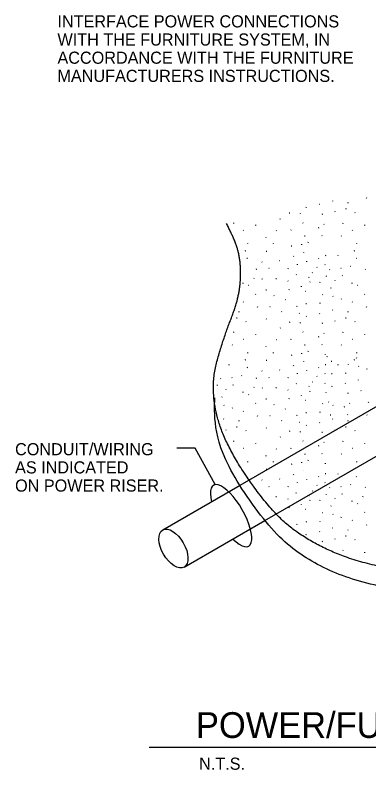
# Model space of a CAD drawing. Extents: x 10309.1 to 10402.7, y 9934 to 9975.2.
# Drawn here: x 10356.1 to 10373.62, y 9935.44 to 9972.81 of the extents above; entities that cross this region are included whole.
import ezdxf

# ---------------------------------------------------------------- set-up
doc = ezdxf.new("R2010")
doc.units = 0
for name, color, linetype in [('G-ANNO-TEXT', 7, 'Continuous'), ('G-DETL-LINE', 7, 'Continuous'), ('G-DETL-OTLN', 7, 'Continuous'), ('G-DETL-PATT', 7, 'Continuous')]:
    doc.layers.add(name, color=color, linetype=linetype)

msp = doc.modelspace()

# ---------------------------------------------------------------- linework, layer by layer
at = {"layer": 'G-ANNO-TEXT'}
msp.add_line((10362.735, 9936.566), (10402.697, 9936.566), dxfattribs=at)
msp.add_lwpolyline([(10366.014, 9949.569), (10365.012, 9951.367), (10364.112, 9951.367)], dxfattribs=at)
msp.add_ellipse((10366.796, 9948.027), major_axis=(-0.869, 1.505), ratio=0.360031, start_param=2.215953, end_param=7.186541, dxfattribs=at)
at = {"layer": 'G-DETL-LINE'}
for p, q in [((10367.242, 9949.532), (10382.211, 9958.175)), ((10368.469, 9947.792), (10383.177, 9956.284)), ((10363.409, 9947.32), (10367.242, 9949.532)), ((10364.47, 9945.483), (10368.469, 9947.792))]:
    msp.add_line(p, q, dxfattribs=at)
msp.add_ellipse((10363.94, 9946.401), major_axis=(0.53, -0.919), ratio=0.531703, dxfattribs=at)
at = {"layer": 'G-DETL-OTLN'}
for p, q in [((10371.839, 9963.603), (10371.828, 9963.614)), ((10373.506, 9963.752), (10373.516, 9963.78)), ((10370.514, 9963.286), (10370.524, 9963.314)), ((10371.193, 9963.43), (10371.178, 9963.444)), ((10372.488, 9963.214), (10372.459, 9963.208)), ((10372.59, 9963.504), (10372.599, 9963.532)), ((10369.705, 9963.005), (10369.676, 9962.999)), ((10370.226, 9962.968), (10370.235, 9962.996)), ((10371.319, 9962.953), (10371.291, 9962.939)), ((10371.957, 9963.067), (10371.943, 9963.081)), ((10372.938, 9963.028), (10372.924, 9963.042)), ((10366.928, 9962.498), (10366.938, 9962.526)), ((10369.232, 9962.707), (10369.241, 9962.735)), ((10370.365, 9962.519), (10370.351, 9962.533)), ((10371.403, 9962.448), (10371.389, 9962.462)), ((10372.328, 9962.498), (10372.338, 9962.526)), ((10367.415, 9962.157), (10367.386, 9962.151)), ((10368.015, 9962.394), (10368.024, 9962.422)), ((10369.043, 9962.127), (10369.029, 9962.141)), ((10369.755, 9962.159), (10369.764, 9962.187)), ((10371.136, 9962.28), (10371.108, 9962.266)), ((10372.815, 9962.157), (10372.786, 9962.151)), ((10373.415, 9962.394), (10373.424, 9962.422)), ((10368.525, 9961.78), (10368.534, 9961.808)), ((10370.464, 9961.87), (10370.435, 9961.863)), ((10371.305, 9961.887), (10371.291, 9961.901)), ((10372.258, 9961.866), (10372.244, 9961.88)), ((10367.622, 9961.48), (10367.631, 9961.508)), ((10368.891, 9961.48), (10368.901, 9961.508)), ((10369.797, 9961.373), (10369.768, 9961.367)), ((10370.292, 9961.441), (10370.301, 9961.469)), ((10370.619, 9961.562), (10370.629, 9961.591)), ((10373.022, 9961.48), (10373.031, 9961.508)), ((10367.507, 9961.138), (10367.478, 9961.132)), ((10368.567, 9961.112), (10368.538, 9961.106)), ((10370.404, 9961.057), (10370.39, 9961.071)), ((10372.907, 9961.138), (10372.878, 9961.132)), ((10367.611, 9960.76), (10367.582, 9960.754)), ((10368.338, 9960.582), (10368.324, 9960.596)), ((10369.213, 9960.639), (10369.199, 9960.653)), ((10369.886, 9960.853), (10369.895, 9960.881)), ((10370.541, 9960.596), (10370.55, 9960.624)), ((10371.136, 9960.751), (10371.122, 9960.765)), ((10371.48, 9960.903), (10371.451, 9960.897)), ((10372.098, 9960.894), (10372.102, 9960.907)), ((10373.011, 9960.76), (10372.982, 9960.754)), ((10368.056, 9960.231), (10368.028, 9960.217)), ((10368.675, 9960.26), (10368.661, 9960.274)), ((10369.624, 9960.253), (10369.634, 9960.281)), ((10370.082, 9960.448), (10370.092, 9960.476)), ((10371.052, 9960.316), (10371.038, 9960.33)), ((10371.46, 9960.456), (10371.446, 9960.47)), ((10371.685, 9960.203), (10371.671, 9960.217)), ((10372.247, 9960.26), (10372.233, 9960.274)), ((10372.725, 9960.358), (10372.711, 9960.372)), ((10373.456, 9960.231), (10373.428, 9960.217)), ((10370.017, 9959.949), (10370.027, 9959.977)), ((10370.645, 9959.818), (10370.655, 9959.846)), ((10370.815, 9960.063), (10370.827, 9960.057)), ((10370.827, 9960.057), (10370.832, 9960.05)), ((10371.518, 9959.871), (10371.527, 9959.899)), ((10372.303, 9959.897), (10372.312, 9959.925)), ((10367.386, 9959.527), (10367.396, 9959.555)), ((10367.923, 9959.766), (10367.933, 9959.794)), ((10368.342, 9959.736), (10368.351, 9959.764)), ((10369.038, 9959.76), (10369.009, 9959.754)), ((10369.619, 9959.639), (10369.605, 9959.653)), ((10370.698, 9959.583), (10370.707, 9959.611)), ((10371.19, 9959.579), (10371.199, 9959.607)), ((10371.957, 9959.678), (10371.943, 9959.692)), ((10372.786, 9959.527), (10372.796, 9959.555)), ((10367.669, 9959.417), (10367.655, 9959.431)), ((10368.541, 9959.198), (10368.512, 9959.192)), ((10369.676, 9959.213), (10369.686, 9959.241)), ((10370.278, 9959.357), (10370.288, 9959.385)), ((10370.503, 9959.133), (10370.475, 9959.127)), ((10371.739, 9959.292), (10371.749, 9959.32)), ((10373.069, 9959.417), (10373.055, 9959.431)), ((10368.023, 9958.986), (10368.009, 9959)), ((10368.926, 9958.921), (10368.912, 9958.935)), ((10369.496, 9958.715), (10369.467, 9958.709)), ((10371.342, 9958.96), (10371.328, 9958.974)), ((10371.852, 9958.881), (10371.838, 9958.896)), ((10372.25, 9958.743), (10372.259, 9958.771)), ((10373.423, 9958.986), (10373.409, 9959)), ((10367.408, 9958.594), (10367.394, 9958.608)), ((10368.106, 9958.352), (10368.116, 9958.38)), ((10368.737, 9958.376), (10368.708, 9958.37)), ((10370.056, 9958.391), (10370.065, 9958.419)), ((10370.53, 9958.519), (10370.501, 9958.513)), ((10371.203, 9958.534), (10371.212, 9958.563)), ((10372.808, 9958.594), (10372.794, 9958.608)), ((10373.506, 9958.352), (10373.516, 9958.38)), ((10367.19, 9958.104), (10367.199, 9958.132)), ((10369.297, 9958.117), (10369.306, 9958.145)), ((10370.182, 9958.033), (10370.168, 9958.047)), ((10371.193, 9958.03), (10371.178, 9958.044)), ((10371.839, 9958.203), (10371.825, 9958.217)), ((10372.59, 9958.104), (10372.599, 9958.132)), ((10367.088, 9957.814), (10367.059, 9957.808)), ((10367.538, 9957.628), (10367.524, 9957.642)), ((10368.546, 9957.759), (10368.532, 9957.773)), ((10369.705, 9957.605), (10369.676, 9957.599)), ((10370.226, 9957.568), (10370.235, 9957.596)), ((10370.514, 9957.886), (10370.524, 9957.914)), ((10371.957, 9957.667), (10371.943, 9957.681)), ((10372.488, 9957.814), (10372.459, 9957.808)), ((10372.938, 9957.628), (10372.924, 9957.642)), ((10369.232, 9957.307), (10369.241, 9957.335)), ((10371.319, 9957.553), (10371.291, 9957.539)), ((10366.928, 9957.098), (10366.938, 9957.126)), ((10368.015, 9956.994), (10368.024, 9957.022)), ((10370.365, 9957.119), (10370.351, 9957.133)), ((10371.136, 9956.88), (10371.108, 9956.866)), ((10371.403, 9957.048), (10371.389, 9957.062)), ((10372.328, 9957.098), (10372.338, 9957.126)), ((10373.415, 9956.994), (10373.424, 9957.022)), ((10366.858, 9956.466), (10366.844, 9956.48)), ((10367.415, 9956.757), (10367.386, 9956.751)), ((10369.043, 9956.727), (10369.029, 9956.741)), ((10369.755, 9956.759), (10369.764, 9956.787)), ((10370.464, 9956.47), (10370.435, 9956.463)), ((10371.305, 9956.487), (10371.291, 9956.501)), ((10372.258, 9956.466), (10372.244, 9956.48)), ((10372.815, 9956.757), (10372.786, 9956.751)), ((10367.622, 9956.08), (10367.631, 9956.108)), ((10368.525, 9956.38), (10368.534, 9956.408)), ((10368.891, 9956.08), (10368.901, 9956.108)), ((10370.619, 9956.162), (10370.629, 9956.191)), ((10373.022, 9956.08), (10373.031, 9956.108)), ((10367.507, 9955.738), (10367.478, 9955.732)), ((10369.797, 9955.973), (10369.768, 9955.967)), ((10370.292, 9956.041), (10370.301, 9956.069)), ((10371.465, 9956.002), (10371.474, 9956.03)), ((10371.552, 9955.893), (10371.562, 9955.921)), ((10372.907, 9955.738), (10372.878, 9955.732)), ((10373.013, 9955.828), (10373.023, 9955.856)), ((10366.693, 9955.479), (10366.702, 9955.507)), ((10367.611, 9955.36), (10367.582, 9955.354)), ((10368.567, 9955.712), (10368.538, 9955.706)), ((10369.886, 9955.453), (10369.895, 9955.481)), ((10370.404, 9955.657), (10370.39, 9955.671)), ((10371.136, 9955.351), (10371.122, 9955.365)), ((10371.48, 9955.503), (10371.451, 9955.497)), ((10371.777, 9955.669), (10371.748, 9955.663)), ((10372.093, 9955.479), (10372.102, 9955.507)), ((10372.616, 9955.496), (10372.602, 9955.51)), ((10373.126, 9955.418), (10373.112, 9955.432)), ((10367.325, 9954.958), (10367.311, 9954.972)), ((10368.338, 9955.182), (10368.324, 9955.196)), ((10369.213, 9955.239), (10369.199, 9955.253)), ((10370.082, 9955.048), (10370.092, 9955.076)), ((10370.541, 9955.196), (10370.55, 9955.224)), ((10371.46, 9955.056), (10371.446, 9955.07)), ((10371.803, 9955.056), (10371.774, 9955.05)), ((10372.477, 9955.071), (10372.486, 9955.099)), ((10373.524, 9955.28), (10373.533, 9955.308)), ((10366.285, 9954.803), (10366.271, 9954.817)), ((10366.847, 9954.86), (10366.833, 9954.874)), ((10368.056, 9954.831), (10368.028, 9954.817)), ((10368.675, 9954.86), (10368.661, 9954.874)), ((10369.624, 9954.853), (10369.634, 9954.881)), ((10370.815, 9954.663), (10370.827, 9954.657)), ((10370.827, 9954.657), (10370.832, 9954.65)), ((10371.052, 9954.916), (10371.038, 9954.93)), ((10373.113, 9954.739), (10373.099, 9954.753)), ((10366.118, 9954.471), (10366.127, 9954.499)), ((10366.557, 9954.278), (10366.543, 9954.292)), ((10366.903, 9954.497), (10366.912, 9954.525)), ((10367.923, 9954.366), (10367.933, 9954.394)), ((10368.342, 9954.336), (10368.351, 9954.364)), ((10369.038, 9954.36), (10369.009, 9954.354)), ((10369.619, 9954.239), (10369.605, 9954.253)), ((10370.017, 9954.549), (10370.027, 9954.577)), ((10370.645, 9954.418), (10370.655, 9954.446)), ((10371.456, 9954.569), (10371.442, 9954.583)), ((10371.788, 9954.422), (10371.798, 9954.45)), ((10372.466, 9954.567), (10372.452, 9954.581)), ((10366.339, 9953.892), (10366.349, 9953.92)), ((10367.386, 9954.127), (10367.396, 9954.155)), ((10367.669, 9954.017), (10367.655, 9954.031)), ((10370.278, 9953.957), (10370.288, 9953.985)), ((10370.698, 9954.183), (10370.707, 9954.211)), ((10371.5, 9954.105), (10371.509, 9954.133)), ((10372.593, 9954.09), (10372.565, 9954.076)), ((10373.231, 9954.204), (10373.217, 9954.218)), ((10366.452, 9953.481), (10366.438, 9953.496)), ((10368.023, 9953.586), (10368.009, 9953.6)), ((10368.541, 9953.798), (10368.512, 9953.792)), ((10368.926, 9953.521), (10368.912, 9953.535)), ((10369.676, 9953.813), (10369.686, 9953.841)), ((10370.503, 9953.733), (10370.475, 9953.727)), ((10371.342, 9953.56), (10371.328, 9953.574)), ((10371.639, 9953.655), (10371.625, 9953.669)), ((10371.852, 9953.481), (10371.838, 9953.496)), ((10372.677, 9953.584), (10372.663, 9953.599)), ((10373.602, 9953.635), (10373.611, 9953.663)), ((10366.85, 9953.343), (10366.859, 9953.371)), ((10367.408, 9953.194), (10367.394, 9953.208)), ((10369.496, 9953.315), (10369.467, 9953.309)), ((10370.53, 9953.119), (10370.501, 9953.113)), ((10371.203, 9953.134), (10371.212, 9953.163)), ((10372.41, 9953.416), (10372.382, 9953.402)), ((10366.439, 9952.803), (10366.425, 9952.817)), ((10367.19, 9952.704), (10367.199, 9952.732)), ((10368.106, 9952.952), (10368.116, 9952.98)), ((10368.737, 9952.976), (10368.708, 9952.97)), ((10369.297, 9952.717), (10369.306, 9952.745)), ((10370.056, 9952.991), (10370.065, 9953.019)), ((10371.738, 9953.006), (10371.709, 9953)), ((10371.839, 9952.803), (10371.825, 9952.817)), ((10372.579, 9953.023), (10372.565, 9953.037)), ((10372.59, 9952.704), (10372.599, 9952.732)), ((10373.532, 9953.002), (10373.518, 9953.016)), ((10367.088, 9952.414), (10367.059, 9952.408)), ((10368.546, 9952.359), (10368.532, 9952.373)), ((10370.182, 9952.633), (10370.168, 9952.647)), ((10370.514, 9952.486), (10370.524, 9952.514)), ((10371.193, 9952.63), (10371.178, 9952.644)), ((10372.488, 9952.414), (10372.459, 9952.408)), ((10366.557, 9952.267), (10366.543, 9952.281)), ((10367.538, 9952.228), (10367.524, 9952.242)), ((10369.705, 9952.205), (10369.676, 9952.199)), ((10370.226, 9952.168), (10370.235, 9952.196)), ((10371.319, 9952.153), (10371.291, 9952.139)), ((10371.957, 9952.267), (10371.943, 9952.281)), ((10372.938, 9952.228), (10372.924, 9952.242)), ((10366.928, 9951.698), (10366.938, 9951.726)), ((10368.015, 9951.594), (10368.024, 9951.622)), ((10369.232, 9951.907), (10369.241, 9951.935)), ((10370.365, 9951.719), (10370.351, 9951.733)), ((10371.403, 9951.648), (10371.389, 9951.662)), ((10372.328, 9951.698), (10372.338, 9951.726)), ((10373.415, 9951.594), (10373.424, 9951.622)), ((10367.415, 9951.357), (10367.386, 9951.351)), ((10369.043, 9951.327), (10369.029, 9951.341)), ((10369.755, 9951.359), (10369.764, 9951.387)), ((10371.136, 9951.48), (10371.108, 9951.466)), ((10372.815, 9951.357), (10372.786, 9951.351)), ((10368.525, 9950.98), (10368.534, 9951.008)), ((10370.464, 9951.07), (10370.435, 9951.063)), ((10371.305, 9951.087), (10371.291, 9951.101)), ((10372.258, 9951.066), (10372.244, 9951.08)), ((10367.622, 9950.68), (10367.631, 9950.708)), ((10368.891, 9950.68), (10368.901, 9950.708)), ((10369.797, 9950.573), (10369.768, 9950.567)), ((10370.292, 9950.641), (10370.301, 9950.669)), ((10370.619, 9950.762), (10370.629, 9950.791)), ((10371.465, 9950.602), (10371.474, 9950.63)), ((10373.022, 9950.68), (10373.031, 9950.708)), ((10368.567, 9950.312), (10368.538, 9950.306)), ((10370.404, 9950.257), (10370.39, 9950.271)), ((10372.907, 9950.338), (10372.878, 9950.332)), ((10368.338, 9949.782), (10368.324, 9949.796)), ((10369.213, 9949.839), (10369.199, 9949.853)), ((10369.886, 9950.053), (10369.895, 9950.081)), ((10370.541, 9949.796), (10370.55, 9949.824)), ((10371.136, 9949.951), (10371.122, 9949.965)), ((10371.48, 9950.103), (10371.451, 9950.097)), ((10372.093, 9950.079), (10372.102, 9950.107)), ((10373.011, 9949.96), (10372.982, 9949.954)), ((10368.675, 9949.46), (10368.661, 9949.474)), ((10369.624, 9949.453), (10369.634, 9949.481)), ((10370.082, 9949.648), (10370.092, 9949.676)), ((10371.052, 9949.516), (10371.038, 9949.53)), ((10371.46, 9949.656), (10371.446, 9949.67)), ((10371.685, 9949.403), (10371.671, 9949.417)), ((10372.247, 9949.46), (10372.233, 9949.474)), ((10372.725, 9949.558), (10372.711, 9949.572)), ((10373.456, 9949.431), (10373.428, 9949.417)), ((10370.017, 9949.149), (10370.027, 9949.177)), ((10370.645, 9949.018), (10370.655, 9949.046)), ((10370.815, 9949.263), (10370.827, 9949.257)), ((10370.827, 9949.257), (10370.832, 9949.25)), ((10371.518, 9949.071), (10371.527, 9949.099)), ((10372.303, 9949.097), (10372.312, 9949.125)), ((10373.323, 9948.966), (10373.333, 9948.994)), ((10369.038, 9948.96), (10369.009, 9948.954)), ((10369.619, 9948.839), (10369.605, 9948.853)), ((10370.698, 9948.783), (10370.707, 9948.811)), ((10371.19, 9948.779), (10371.199, 9948.807)), ((10371.957, 9948.878), (10371.943, 9948.892)), ((10372.786, 9948.727), (10372.796, 9948.755)), ((10373.069, 9948.617), (10373.055, 9948.631)), ((10369.676, 9948.413), (10369.686, 9948.441)), ((10370.278, 9948.557), (10370.288, 9948.585)), ((10370.503, 9948.333), (10370.475, 9948.327)), ((10371.739, 9948.492), (10371.749, 9948.52)), ((10371.342, 9948.16), (10371.328, 9948.174)), ((10371.852, 9948.081), (10371.838, 9948.096)), ((10372.25, 9947.943), (10372.259, 9947.971)), ((10373.423, 9948.186), (10373.409, 9948.2)), ((10370.056, 9947.591), (10370.065, 9947.619)), ((10370.53, 9947.719), (10370.501, 9947.713)), ((10371.203, 9947.734), (10371.212, 9947.763)), ((10372.808, 9947.794), (10372.794, 9947.808)), ((10373.506, 9947.552), (10373.516, 9947.58)), ((10371.193, 9947.23), (10371.178, 9947.244)), ((10371.839, 9947.403), (10371.825, 9947.417)), ((10372.59, 9947.304), (10372.599, 9947.332)), ((10370.514, 9947.086), (10370.524, 9947.114)), ((10371.319, 9946.753), (10371.291, 9946.739)), ((10371.957, 9946.867), (10371.943, 9946.881)), ((10372.488, 9947.014), (10372.459, 9947.008)), ((10372.938, 9946.828), (10372.924, 9946.842)), ((10372.328, 9946.298), (10372.338, 9946.326)), ((10373.415, 9946.194), (10373.424, 9946.222))]:
    msp.add_line(p, q, dxfattribs=at)
at = {"layer": 'G-DETL-PATT'}
for points, degree in [([(10399.089, 9957.535), (10398.602, 9956.691), (10397.405, 9956.001), (10394.152, 9954.997), (10392.301, 9954.688), (10388.968, 9953.326), (10387.24, 9951.655), (10384.895, 9949.364), (10383.291, 9948.002), (10380.329, 9946.207), (10378.663, 9945.526), (10376.379, 9945.155), (10373.232, 9945.65), (10370.702, 9946.703), (10368.727, 9948.25), (10366.382, 9951.716), (10365.765, 9954.44), (10366.382, 9956.73), (10367.185, 9958.773), (10367.308, 9960.321), (10367.061, 9961.559), (10366.567, 9962.487)], 2), ([(10399.089, 9956.523), (10398.602, 9955.679), (10397.405, 9954.988), (10394.152, 9953.985), (10392.301, 9953.675), (10388.968, 9952.313), (10387.24, 9950.642), (10384.895, 9948.352), (10383.291, 9946.99), (10380.329, 9945.195), (10378.663, 9944.514), (10376.379, 9944.143), (10373.232, 9944.638), (10370.702, 9945.69), (10368.727, 9947.238), (10366.382, 9950.704), (10365.928, 9952.709), (10365.98, 9953.701), (10365.996, 9953.87)], 3)]:
    msp.add_open_spline(points, degree=degree, dxfattribs=at)

# ---------------------------------------------------------------- texts
at = {"layer": 'G-ANNO-TEXT'}
for s, height, p in [('INTERFACE POWER CONNECTIONS', 0.6, (10358.195, 9972.205)), ('WITH THE FURNITURE SYSTEM, IN', 0.6, (10358.195, 9971.305)), ('ACCORDANCE WITH THE FURNITURE', 0.6, (10358.195, 9970.405)), ('MANUFACTURERS INSTRUCTIONS.', 0.6, (10358.195, 9969.505)), ('CONDUIT/WIRING', 0.6, (10356.095, 9951.019)), ('AS INDICATED', 0.6, (10356.095, 9950.119)), ('ON POWER RISER.', 0.6, (10356.095, 9949.219)), ('POWER/FURNITURE INTERFACE DETAIL', 1.275, (10365.056, 9937.022)), ('N.T.S.', 0.6, (10365.211, 9935.447))]:
    msp.add_text(s, height=height, dxfattribs=at).set_placement(p)

doc.saveas('drawing.dxf')
